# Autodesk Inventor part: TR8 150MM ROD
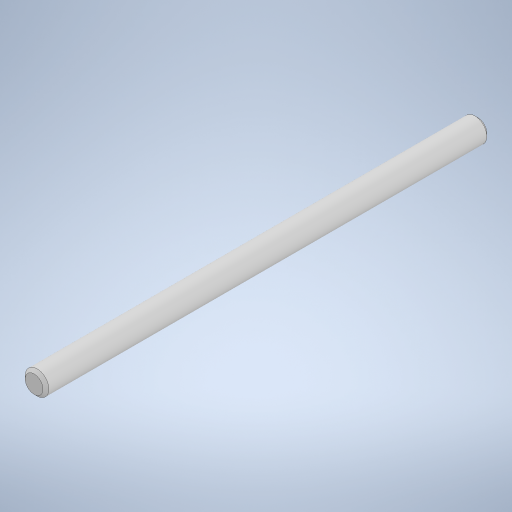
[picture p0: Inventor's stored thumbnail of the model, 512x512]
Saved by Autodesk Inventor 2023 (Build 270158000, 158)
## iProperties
Created: 2025-07
Part Number: TR8 150MM ROD
Material: Generic
Document SubType Name: Modeling
Designer: erjon
Density: 1 g/cm^3
Appearance: Default
Author: erjon
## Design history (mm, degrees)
feature "Base1"
body "Solid1"
